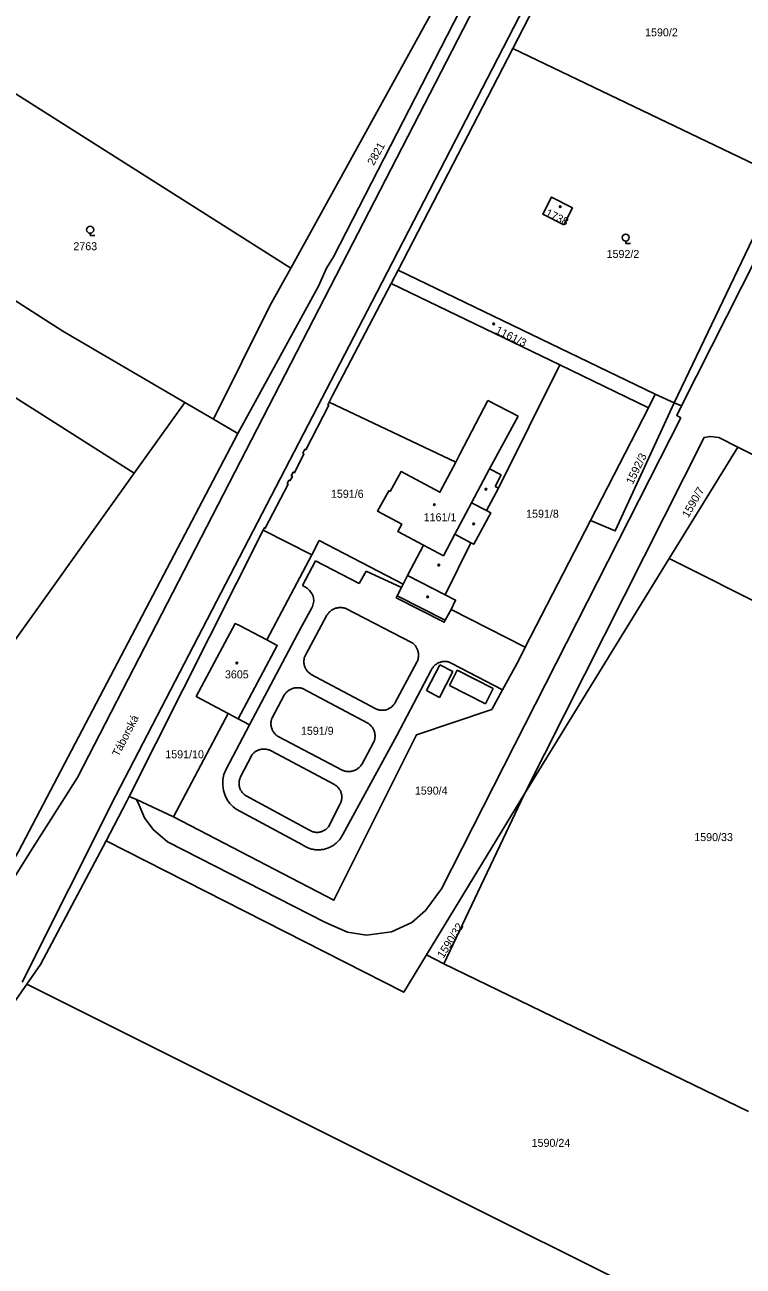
# Model space of a CAD drawing. Extents: x -679220 to -673243, y -1075091 to -1066557.
# Drawn here: x -677779.5 to -677626.7, y -1071876.4 to -1071612.6 of the extents above; entities that cross this region are included whole.
import ezdxf

# ---------------------------------------------------------------- set-up
doc = ezdxf.new("R2010")
doc.units = 0
for name, color, linetype in [('Hranice parcel', 7, 'Continuous'), ('Parcelní čísla', 7, 'Continuous'), ('Pop  PČ popisy', 7, 'Continuous'), ('Vnitřní kresba', 7, 'Continuous'), ('Značky budov', 7, 'Continuous'), ('Značky kultur', 7, 'Continuous')]:
    doc.layers.add(name, color=color, linetype=linetype)

msp = doc.modelspace()

# ---------------------------------------------------------------- linework, layer by layer
at = {"layer": 'Hranice parcel'}
for p, q in [((-677675.7, -1071617.62), (-677659.4, -1071586.1)), ((-677675.7, -1071617.62), (-677700.06, -1071664.74)), ((-677618.5, -1071645.05), (-677675.7, -1071617.62)), ((-677793.05, -1071619.95), (-677722.95, -1071664.32)), ((-677618.5, -1071645.05), (-677641.36, -1071692.91)), ((-677701.57, -1071667.56), (-677700.06, -1071664.74)), ((-677700.06, -1071664.74), (-677645.4, -1071691.12)), ((-677756.22, -1071707.84), (-677819.64, -1071667.71)), ((-677665.7, -1071684.86), (-677701.57, -1071667.56)), ((-677646.86, -1071693.97), (-677665.7, -1071684.86)), ((-677646.86, -1071693.97), (-677645.4, -1071691.12)), ((-677645.4, -1071691.12), (-677641.36, -1071692.91)), ((-677745.49, -1071692.83), (-677756.22, -1071707.84)), ((-677739.36, -1071696.41), (-677745.49, -1071692.83)), ((-677659.15, -1071717.9), (-677646.86, -1071693.97)), ((-677739.36, -1071696.41), (-677734.17, -1071699.43)), ((-677627.85, -1071702.34), (-677642.42, -1071725.99)), ((-677627.85, -1071702.34), (-677620.62, -1071705.96)), ((-677756.22, -1071707.84), (-677824.86, -1071803.81)), ((-677659.15, -1071717.9), (-677673.05, -1071744.83)), ((-677728.78, -1071719.96), (-677757.32, -1071776.61)), ((-677728.78, -1071719.96), (-677718.47, -1071725.21)), ((-677718.47, -1071725.21), (-677728.03, -1071743.31)), ((-677642.42, -1071725.99), (-677673.25, -1071776.04)), ((-677576.6, -1071759.04), (-677642.42, -1071725.99)), ((-677688.85, -1071736.82), (-677673.05, -1071744.83)), ((-677736.28, -1071758.92), (-677747.89, -1071780.9)), ((-677694.09, -1071810.25), (-677673.25, -1071776.04)), ((-677690.35, -1071812.12), (-677673.25, -1071776.04)), ((-677755.75, -1071777.25), (-677757.32, -1071776.61)), ((-677747.89, -1071780.9), (-677755.75, -1071777.25)), ((-677690.35, -1071812.12), (-677694.09, -1071810.25)), ((-677625.55, -1071843.55), (-677690.35, -1071812.12))]:
    msp.add_line(p, q, dxfattribs=at)
for points in [[(-677698.2, -1071587.54), (-677691.4, -1071597.52), (-677689.84, -1071604.27), (-677722.95, -1071664.32)], [(-677679.36, -1071592.98), (-677680.93, -1071595.81), (-677681.57, -1071599.11), (-677713.84, -1071661.87), (-677715.32, -1071664.31), (-677717.06, -1071668.11), (-677734.17, -1071699.43)], [(-677664.83, -1071655.1), (-677663.03, -1071651.51), (-677667.46, -1071649.22), (-677669.29, -1071652.86), (-677664.83, -1071655.1)], [(-677811.07, -1071652.31), (-677771.4, -1071677.73), (-677745.49, -1071692.83)], [(-677722.95, -1071664.32), (-677727.35, -1071672.3), (-677739.36, -1071696.41)], [(-677701.57, -1071667.56), (-677714.05, -1071691.4), (-677714.77, -1071692.82)], [(-677688.85, -1071736.82), (-677687.88, -1071734.84), (-677690.1, -1071733.71), (-677684.65, -1071722.65), (-677684.02, -1071722.98), (-677680.41, -1071716.3), (-677681.29, -1071715.83), (-677678.78, -1071711.06), (-677665.7, -1071684.86)], [(-677641.36, -1071692.91), (-677639.79, -1071693.55), (-677640.85, -1071695.65), (-677639.97, -1071696.12), (-677690.9, -1071796.21), (-677694.24, -1071800.78), (-677697.21, -1071803.39), (-677701.52, -1071805.32), (-677706.8, -1071806.02), (-677710.87, -1071805.39), (-677715.51, -1071803.35), (-677749.17, -1071786.23), (-677752.18, -1071783.61), (-677754.07, -1071781.12), (-677755.18, -1071778.44), (-677755.75, -1071777.25)], [(-677714.77, -1071692.82), (-677715.03, -1071693.32), (-677714.85, -1071693.41), (-677719.75, -1071702.9), (-677719.93, -1071702.81), (-677720.36, -1071703.65), (-677720.18, -1071703.74), (-677722.17, -1071707.77), (-677722.42, -1071707.64), (-677722.83, -1071708.44), (-677722.58, -1071708.56), (-677723.14, -1071709.48), (-677723.32, -1071709.39), (-677723.69, -1071710.1), (-677723.5, -1071710.19), (-677728.35, -1071719.57), (-677728.53, -1071719.48), (-677728.78, -1071719.96)], [(-677714.77, -1071692.82), (-677687.83, -1071705.51), (-677691.21, -1071711.92), (-677699.48, -1071707.54), (-677701.8, -1071711.75), (-677702.06, -1071711.6), (-677704.47, -1071715.98), (-677699.33, -1071718.71), (-677700.16, -1071720.29), (-677694.72, -1071723.15), (-677698.11, -1071729.64), (-677699.04, -1071731.47)], [(-677641.36, -1071692.91), (-677653.91, -1071720.16), (-677659.15, -1071717.9)], [(-677734.17, -1071699.43), (-677780.84, -1071788.29), (-677785.81, -1071796.6), (-677796.28, -1071814.23), (-677801.03, -1071820.85)], [(-677673.25, -1071776.04), (-677635.03, -1071700.33), (-677633.76, -1071700.05), (-677631.86, -1071700.33), (-677627.85, -1071702.34)], [(-677718.47, -1071725.21), (-677716.89, -1071722.21), (-677699.04, -1071731.47)], [(-677699.04, -1071731.47), (-677699.41, -1071732.17), (-677700.29, -1071733.93), (-677700.51, -1071734.35), (-677690.28, -1071739.55), (-677690.07, -1071739.14), (-677688.85, -1071736.82)], [(-677736.28, -1071758.92), (-677743.02, -1071755.33), (-677734.77, -1071739.82), (-677733.82, -1071740.27), (-677728.03, -1071743.31)], [(-677728.03, -1071743.31), (-677725.82, -1071744.47), (-677734.15, -1071760.05), (-677736.28, -1071758.92)], [(-677673.05, -1071744.83), (-677674.41, -1071747.63), (-677677.87, -1071753.9), (-677680.19, -1071758.12), (-677696.22, -1071763.45), (-677713.74, -1071798.64), (-677747.89, -1071780.9)], [(-677757.32, -1071776.61), (-677757.9, -1071777.68), (-677762.22, -1071786)], [(-677779.1, -1071816.48), (-677776.17, -1071812.28), (-677762.22, -1071786)], [(-677762.22, -1071786), (-677698.91, -1071818.16), (-677694.09, -1071810.25)], [(-677809.4, -1071859.4), (-677801.45, -1071848.53), (-677779.1, -1071816.48)], [(-677576, -1071917.67), (-677677.67, -1071867.11), (-677779.1, -1071816.48)]]:
    msp.add_lwpolyline(points, dxfattribs=at)
at = {"layer": 'Vnitřní kresba'}
for p, q in [((-677658.49, -1071559.68), (-677713.36, -1071666.01)), ((-677704.66, -1071669.46), (-677649.28, -1071562.45)), ((-677601.83, -1071618.35), (-677639.79, -1071693.55)), ((-677713.36, -1071666.01), (-677768.3, -1071772.54)), ((-677760.23, -1071776.53), (-677704.66, -1071669.46)), ((-677686.96, -1071703.87), (-677681.03, -1071692.44)), ((-677681.03, -1071692.44), (-677674.59, -1071695.73)), ((-677674.59, -1071695.73), (-677680.66, -1071706.92)), ((-677686.96, -1071703.87), (-677687.83, -1071705.51)), ((-677680.66, -1071706.92), (-677684.47, -1071714.15)), ((-677680.66, -1071706.92), (-677678.19, -1071708.23)), ((-677678.19, -1071708.23), (-677679.48, -1071710.69)), ((-677679.48, -1071710.69), (-677678.78, -1071711.06)), ((-677684.47, -1071714.15), (-677688.02, -1071720.87)), ((-677684.47, -1071714.15), (-677681.29, -1071715.83)), ((-677690.42, -1071725.42), (-677694.72, -1071723.15)), ((-677688.02, -1071720.87), (-677690.42, -1071725.42)), ((-677688.02, -1071720.87), (-677684.65, -1071722.65)), ((-677720.43, -1071731.72), (-677717.67, -1071726.5)), ((-677717.67, -1071726.5), (-677708.37, -1071731.35)), ((-677708.37, -1071731.35), (-677706.91, -1071728.7)), ((-677706.91, -1071728.7), (-677699.41, -1071732.17)), ((-677690.1, -1071733.71), (-677698.11, -1071729.64)), ((-677719.43, -1071732.34), (-677720.43, -1071731.72)), ((-677719.43, -1071732.34), (-677718.92, -1071732.79)), ((-677718.92, -1071732.79), (-677718.46, -1071733.42)), ((-677718.46, -1071733.42), (-677718.2, -1071734.01)), ((-677720.84, -1071740.86), (-677718.42, -1071736.47)), ((-677718.29, -1071736.19), (-677718.42, -1071736.47)), ((-677718.14, -1071735.64), (-677718.29, -1071736.19)), ((-677718.2, -1071734.01), (-677718.12, -1071734.38)), ((-677718.06, -1071735.08), (-677718.14, -1071735.64)), ((-677718.12, -1071734.38), (-677718.06, -1071735.08)), ((-677690.07, -1071739.14), (-677700.29, -1071733.93)), ((-677719.83, -1071746.56), (-677715.23, -1071738.05)), ((-677711.35, -1071736.59), (-677697.11, -1071743.91)), ((-677731.72, -1071761.34), (-677720.84, -1071740.86)), ((-677696.09, -1071748.02), (-677700.74, -1071756.62)), ((-677691.24, -1071748.63), (-677694.09, -1071754.07)), ((-677688.45, -1071750.01), (-677691.24, -1071748.63)), ((-677677.87, -1071753.9), (-677688.65, -1071748.29)), ((-677704.86, -1071757.93), (-677718.7, -1071750.56)), ((-677700.4, -1071763.63), (-677693.06, -1071749.76)), ((-677691.29, -1071755.55), (-677688.45, -1071750.01)), ((-677689.2, -1071753.01), (-677687.53, -1071749.76)), ((-677687.53, -1071749.76), (-677679.88, -1071753.61)), ((-677720.26, -1071753.68), (-677706.56, -1071760.97)), ((-677694.09, -1071754.07), (-677691.29, -1071755.55)), ((-677681.5, -1071756.87), (-677689.2, -1071753.01)), ((-677679.88, -1071753.61), (-677681.5, -1071756.87)), ((-677726.89, -1071759.84), (-677724.33, -1071755.03)), ((-677731.72, -1071761.34), (-677734.15, -1071760.05)), ((-677731.72, -1071761.34), (-677736.7, -1071770.76)), ((-677725.63, -1071763.83), (-677711.86, -1071771.03)), ((-677711.87, -1071784.68), (-677700.4, -1071763.63)), ((-677707.84, -1071769.75), (-677705.31, -1071765.13)), ((-677733.59, -1071772.41), (-677731.3, -1071767.92)), ((-677727.11, -1071766.88), (-677713.63, -1071774.06)), ((-677737.14, -1071771.93), (-677736.7, -1071770.76)), ((-677778.26, -1071788.24), (-677768.3, -1071772.54)), ((-677737.4, -1071774.19), (-677737.36, -1071772.99)), ((-677737.36, -1071772.99), (-677737.14, -1071771.93)), ((-677737.24, -1071775.34), (-677737.4, -1071774.19)), ((-677736.89, -1071776.37), (-677737.24, -1071775.34)), ((-677760.23, -1071776.53), (-677780.06, -1071816)), ((-677736.45, -1071777.26), (-677736.89, -1071776.37)), ((-677735.9, -1071778.05), (-677736.45, -1071777.26)), ((-677735.18, -1071778.79), (-677735.9, -1071778.05)), ((-677719.09, -1071783.67), (-677732.43, -1071776.42)), ((-677712.41, -1071778.12), (-677714.94, -1071783.02)), ((-677734.55, -1071779.28), (-677735.18, -1071778.79)), ((-677720.43, -1071786.85), (-677734.55, -1071779.28)), ((-677795.14, -1071815.04), (-677778.26, -1071788.24))]:
    msp.add_line(p, q, dxfattribs=at)
for points in [[(-677715.23, -1071738.05), (-677715.14, -1071737.92), (-677715.05, -1071737.79), (-677714.95, -1071737.66), (-677714.85, -1071737.54), (-677714.74, -1071737.42), (-677714.62, -1071737.31), (-677714.51, -1071737.21), (-677714.38, -1071737.11), (-677714.25, -1071737.01), (-677714.12, -1071736.93), (-677713.98, -1071736.85), (-677713.84, -1071736.77), (-677713.69, -1071736.71), (-677713.54, -1071736.65), (-677713.39, -1071736.59), (-677713.24, -1071736.55), (-677713.08, -1071736.51), (-677712.93, -1071736.48), (-677712.77, -1071736.46), (-677712.61, -1071736.44), (-677712.45, -1071736.43), (-677712.29, -1071736.43), (-677712.13, -1071736.44), (-677711.97, -1071736.46), (-677711.82, -1071736.48), (-677711.66, -1071736.51), (-677711.5, -1071736.55), (-677711.35, -1071736.59)], [(-677697.11, -1071743.91), (-677696.98, -1071744.01), (-677696.86, -1071744.11), (-677696.74, -1071744.22), (-677696.63, -1071744.33), (-677696.53, -1071744.45), (-677696.43, -1071744.57), (-677696.34, -1071744.7), (-677696.25, -1071744.83), (-677696.17, -1071744.97), (-677696.09, -1071745.11), (-677696.03, -1071745.25), (-677695.97, -1071745.4), (-677695.91, -1071745.55), (-677695.87, -1071745.7), (-677695.83, -1071745.85), (-677695.8, -1071746.01), (-677695.78, -1071746.17), (-677695.76, -1071746.33), (-677695.75, -1071746.49), (-677695.75, -1071746.64), (-677695.76, -1071746.8), (-677695.77, -1071746.96), (-677695.8, -1071747.12), (-677695.83, -1071747.27), (-677695.86, -1071747.43), (-677695.91, -1071747.58), (-677695.96, -1071747.73), (-677696.02, -1071747.88), (-677696.09, -1071748.02)], [(-677718.7, -1071750.56), (-677718.83, -1071750.47), (-677718.96, -1071750.38), (-677719.08, -1071750.28), (-677719.19, -1071750.17), (-677719.3, -1071750.06), (-677719.41, -1071749.94), (-677719.51, -1071749.82), (-677719.6, -1071749.7), (-677719.68, -1071749.56), (-677719.76, -1071749.43), (-677719.84, -1071749.29), (-677719.9, -1071749.15), (-677719.96, -1071749), (-677720.01, -1071748.85), (-677720.05, -1071748.7), (-677720.09, -1071748.55), (-677720.11, -1071748.39), (-677720.13, -1071748.24), (-677720.14, -1071748.08), (-677720.15, -1071747.92), (-677720.14, -1071747.77), (-677720.13, -1071747.61), (-677720.11, -1071747.46), (-677720.08, -1071747.3), (-677720.05, -1071747.15), (-677720, -1071747), (-677719.95, -1071746.85), (-677719.9, -1071746.7), (-677719.83, -1071746.56)], [(-677693.06, -1071749.76), (-677692.99, -1071749.62), (-677692.92, -1071749.48), (-677692.83, -1071749.34), (-677692.74, -1071749.21), (-677692.65, -1071749.08), (-677692.55, -1071748.96), (-677692.44, -1071748.85), (-677692.33, -1071748.74), (-677692.21, -1071748.63), (-677692.09, -1071748.53), (-677691.96, -1071748.44), (-677691.82, -1071748.35), (-677691.69, -1071748.28), (-677691.55, -1071748.2), (-677691.4, -1071748.14), (-677691.25, -1071748.08), (-677691.1, -1071748.03), (-677690.95, -1071747.99), (-677690.8, -1071747.95), (-677690.64, -1071747.93), (-677690.48, -1071747.91), (-677690.33, -1071747.9), (-677690.17, -1071747.89), (-677690.01, -1071747.9), (-677689.85, -1071747.91), (-677689.69, -1071747.93), (-677689.54, -1071747.96), (-677689.38, -1071748), (-677689.23, -1071748.04), (-677689.08, -1071748.09), (-677688.93, -1071748.15), (-677688.79, -1071748.22), (-677688.65, -1071748.29)], [(-677724.33, -1071755.03), (-677724.24, -1071754.89), (-677724.14, -1071754.76), (-677724.03, -1071754.64), (-677723.92, -1071754.51), (-677723.8, -1071754.4), (-677723.68, -1071754.29), (-677723.55, -1071754.18), (-677723.42, -1071754.09), (-677723.28, -1071754), (-677723.14, -1071753.91), (-677722.99, -1071753.83), (-677722.84, -1071753.76), (-677722.69, -1071753.7), (-677722.53, -1071753.64), (-677722.37, -1071753.59), (-677722.21, -1071753.55), (-677722.05, -1071753.52), (-677721.89, -1071753.5), (-677721.72, -1071753.48), (-677721.56, -1071753.47), (-677721.39, -1071753.47), (-677721.23, -1071753.48), (-677721.06, -1071753.49), (-677720.9, -1071753.51), (-677720.74, -1071753.54), (-677720.58, -1071753.58), (-677720.42, -1071753.63), (-677720.26, -1071753.68)], [(-677700.74, -1071756.62), (-677700.82, -1071756.75), (-677700.9, -1071756.89), (-677700.99, -1071757.01), (-677701.08, -1071757.13), (-677701.18, -1071757.25), (-677701.29, -1071757.36), (-677701.4, -1071757.47), (-677701.52, -1071757.57), (-677701.64, -1071757.66), (-677701.77, -1071757.75), (-677701.9, -1071757.83), (-677702.04, -1071757.91), (-677702.17, -1071757.98), (-677702.32, -1071758.04), (-677702.46, -1071758.09), (-677702.61, -1071758.14), (-677702.76, -1071758.18), (-677702.91, -1071758.21), (-677703.06, -1071758.23), (-677703.21, -1071758.25), (-677703.37, -1071758.26), (-677703.52, -1071758.26), (-677703.68, -1071758.25), (-677703.83, -1071758.24), (-677703.98, -1071758.22), (-677704.13, -1071758.19), (-677704.28, -1071758.15), (-677704.43, -1071758.11), (-677704.58, -1071758.06), (-677704.72, -1071758), (-677704.86, -1071757.93)], [(-677725.63, -1071763.83), (-677725.76, -1071763.74), (-677725.89, -1071763.65), (-677726.01, -1071763.55), (-677726.13, -1071763.45), (-677726.24, -1071763.34), (-677726.35, -1071763.22), (-677726.45, -1071763.1), (-677726.54, -1071762.98), (-677726.63, -1071762.85), (-677726.72, -1071762.72), (-677726.79, -1071762.58), (-677726.86, -1071762.44), (-677726.92, -1071762.29), (-677726.98, -1071762.14), (-677727.02, -1071761.99), (-677727.06, -1071761.84), (-677727.1, -1071761.69), (-677727.12, -1071761.53), (-677727.14, -1071761.38), (-677727.15, -1071761.22), (-677727.15, -1071761.06), (-677727.14, -1071760.91), (-677727.13, -1071760.75), (-677727.11, -1071760.59), (-677727.08, -1071760.44), (-677727.04, -1071760.29), (-677727, -1071760.14), (-677726.95, -1071759.99), (-677726.89, -1071759.84)], [(-677706.56, -1071760.97), (-677706.43, -1071761.06), (-677706.3, -1071761.15), (-677706.17, -1071761.25), (-677706.05, -1071761.35), (-677705.94, -1071761.46), (-677705.83, -1071761.58), (-677705.73, -1071761.7), (-677705.63, -1071761.82), (-677705.54, -1071761.95), (-677705.46, -1071762.09), (-677705.38, -1071762.22), (-677705.31, -1071762.37), (-677705.24, -1071762.51), (-677705.19, -1071762.66), (-677705.14, -1071762.81), (-677705.1, -1071762.96), (-677705.06, -1071763.12), (-677705.03, -1071763.27), (-677705.02, -1071763.43), (-677705, -1071763.59), (-677705, -1071763.75), (-677705, -1071763.91), (-677705.02, -1071764.06), (-677705.04, -1071764.22), (-677705.06, -1071764.38), (-677705.1, -1071764.53), (-677705.14, -1071764.69), (-677705.19, -1071764.84), (-677705.25, -1071764.99), (-677705.31, -1071765.13)], [(-677731.3, -1071767.92), (-677731.21, -1071767.79), (-677731.11, -1071767.67), (-677731.01, -1071767.55), (-677730.9, -1071767.43), (-677730.79, -1071767.32), (-677730.67, -1071767.22), (-677730.54, -1071767.12), (-677730.41, -1071767.03), (-677730.28, -1071766.95), (-677730.14, -1071766.87), (-677730, -1071766.8), (-677729.86, -1071766.74), (-677729.71, -1071766.68), (-677729.56, -1071766.63), (-677729.41, -1071766.59), (-677729.25, -1071766.55), (-677729.1, -1071766.53), (-677728.94, -1071766.51), (-677728.78, -1071766.5), (-677728.62, -1071766.49), (-677728.47, -1071766.5), (-677728.31, -1071766.51), (-677728.15, -1071766.53), (-677728, -1071766.56), (-677727.84, -1071766.59), (-677727.69, -1071766.64), (-677727.54, -1071766.69), (-677727.4, -1071766.74), (-677727.25, -1071766.81), (-677727.11, -1071766.88)], [(-677707.84, -1071769.75), (-677707.93, -1071769.88), (-677708.02, -1071770.01), (-677708.12, -1071770.13), (-677708.23, -1071770.25), (-677708.34, -1071770.36), (-677708.46, -1071770.46), (-677708.58, -1071770.56), (-677708.71, -1071770.66), (-677708.84, -1071770.75), (-677708.97, -1071770.83), (-677709.11, -1071770.91), (-677709.25, -1071770.98), (-677709.4, -1071771.04), (-677709.54, -1071771.09), (-677709.69, -1071771.14), (-677709.85, -1071771.18), (-677710, -1071771.21), (-677710.16, -1071771.24), (-677710.31, -1071771.26), (-677710.47, -1071771.27), (-677710.63, -1071771.27), (-677710.79, -1071771.27), (-677710.94, -1071771.26), (-677711.1, -1071771.24), (-677711.26, -1071771.21), (-677711.41, -1071771.18), (-677711.56, -1071771.14), (-677711.71, -1071771.09), (-677711.86, -1071771.03)], [(-677732.43, -1071776.42), (-677732.56, -1071776.34), (-677732.69, -1071776.25), (-677732.81, -1071776.16), (-677732.93, -1071776.06), (-677733.04, -1071775.96), (-677733.15, -1071775.84), (-677733.25, -1071775.73), (-677733.34, -1071775.61), (-677733.43, -1071775.48), (-677733.51, -1071775.35), (-677733.59, -1071775.22), (-677733.66, -1071775.08), (-677733.72, -1071774.94), (-677733.77, -1071774.8), (-677733.82, -1071774.65), (-677733.86, -1071774.5), (-677733.89, -1071774.35), (-677733.91, -1071774.2), (-677733.93, -1071774.05), (-677733.94, -1071773.89), (-677733.94, -1071773.74), (-677733.93, -1071773.58), (-677733.91, -1071773.43), (-677733.89, -1071773.28), (-677733.86, -1071773.13), (-677733.82, -1071772.98), (-677733.77, -1071772.83), (-677733.72, -1071772.69), (-677733.66, -1071772.55), (-677733.59, -1071772.41)], [(-677713.63, -1071774.06), (-677713.5, -1071774.14), (-677713.37, -1071774.23), (-677713.24, -1071774.32), (-677713.12, -1071774.42), (-677713.01, -1071774.53), (-677712.9, -1071774.64), (-677712.79, -1071774.75), (-677712.7, -1071774.88), (-677712.61, -1071775), (-677712.52, -1071775.13), (-677712.44, -1071775.27), (-677712.37, -1071775.41), (-677712.31, -1071775.55), (-677712.25, -1071775.7), (-677712.2, -1071775.84), (-677712.16, -1071776), (-677712.13, -1071776.15), (-677712.1, -1071776.3), (-677712.09, -1071776.46), (-677712.08, -1071776.61), (-677712.08, -1071776.77), (-677712.08, -1071776.93), (-677712.1, -1071777.08), (-677712.12, -1071777.23), (-677712.15, -1071777.39), (-677712.18, -1071777.54), (-677712.23, -1071777.69), (-677712.28, -1071777.83), (-677712.34, -1071777.98), (-677712.41, -1071778.12)], [(-677714.94, -1071783.02), (-677715.04, -1071783.14), (-677715.14, -1071783.25), (-677715.25, -1071783.36), (-677715.36, -1071783.47), (-677715.48, -1071783.56), (-677715.61, -1071783.66), (-677715.74, -1071783.74), (-677715.87, -1071783.82), (-677716.01, -1071783.89), (-677716.15, -1071783.96), (-677716.29, -1071784.01), (-677716.44, -1071784.06), (-677716.58, -1071784.11), (-677716.73, -1071784.14), (-677716.89, -1071784.17), (-677717.04, -1071784.19), (-677717.19, -1071784.2), (-677717.35, -1071784.21), (-677717.5, -1071784.2), (-677717.66, -1071784.19), (-677717.81, -1071784.17), (-677717.96, -1071784.15), (-677718.11, -1071784.11), (-677718.26, -1071784.07), (-677718.41, -1071784.02), (-677718.55, -1071783.97), (-677718.69, -1071783.9), (-677718.83, -1071783.83), (-677718.96, -1071783.75), (-677719.09, -1071783.67)], [(-677711.87, -1071784.68), (-677711.97, -1071784.87), (-677712.07, -1071785.06), (-677712.19, -1071785.24), (-677712.3, -1071785.42), (-677712.43, -1071785.59), (-677712.56, -1071785.76), (-677712.7, -1071785.92), (-677712.84, -1071786.08), (-677712.99, -1071786.23), (-677713.14, -1071786.38), (-677713.3, -1071786.52), (-677713.47, -1071786.66), (-677713.64, -1071786.79), (-677713.81, -1071786.91), (-677713.99, -1071787.03), (-677714.17, -1071787.14), (-677714.36, -1071787.24), (-677714.55, -1071787.33), (-677714.74, -1071787.42), (-677714.94, -1071787.51), (-677715.14, -1071787.58), (-677715.34, -1071787.65), (-677715.55, -1071787.71), (-677715.75, -1071787.76), (-677715.96, -1071787.81), (-677716.17, -1071787.84), (-677716.38, -1071787.87), (-677716.6, -1071787.89), (-677716.81, -1071787.91), (-677717.02, -1071787.91), (-677717.24, -1071787.91), (-677717.45, -1071787.9), (-677717.66, -1071787.88), (-677717.87, -1071787.86), (-677718.09, -1071787.83), (-677718.29, -1071787.79), (-677718.5, -1071787.74), (-677718.71, -1071787.68), (-677718.91, -1071787.62), (-677719.11, -1071787.55), (-677719.31, -1071787.47), (-677719.51, -1071787.38), (-677719.7, -1071787.29), (-677719.89, -1071787.19), (-677720.07, -1071787.08), (-677720.25, -1071786.97), (-677720.43, -1071786.85)]]:
    msp.add_lwpolyline(points, dxfattribs=at)
at = {"layer": 'Značky budov'}
for centre in [(-677665.62, -1071651.24), (-677679.79, -1071676.15), (-677681.43, -1071711.29), (-677692.39, -1071714.58), (-677684.02, -1071718.65), (-677691.45, -1071727.42), (-677693.8, -1071734.16), (-677734.4, -1071748.23)]:
    msp.add_circle(centre, 0.175, dxfattribs=at)
at = {"layer": 'Značky kultur'}
for p, q in [((-677765.6, -1071656.9), (-677765.6, -1071657.4)), ((-677765.6, -1071657.4), (-677764.6, -1071657.4)), ((-677651.69, -1071658.57), (-677651.69, -1071659.07)), ((-677651.69, -1071659.07), (-677650.69, -1071659.07))]:
    msp.add_line(p, q, dxfattribs=at)
for centre in [(-677765.6, -1071656.15), (-677651.69, -1071657.82)]:
    msp.add_circle(centre, 0.75, dxfattribs=at)

# ---------------------------------------------------------------- texts
at = {"layer": 'Parcelní čísla'}
for s, p in [('1590/2', (-677647.57, -1071615.05)), ('2763', (-677769.17, -1071660.5)), ('1592/2', (-677655.75, -1071662.14)), ('1591/6', (-677714.39, -1071713.11)), ('1161/1', (-677694.66, -1071718.09)), ('1591/8', (-677672.87, -1071717.34)), ('3605', (-677736.94, -1071751.48)), ('1591/9', (-677720.77, -1071763.47)), ('1591/10', (-677749.62, -1071768.46)), ('1590/4', (-677696.53, -1071776.18)), ('1590/33', (-677637.11, -1071786.06)), ('1590/24', (-677671.7, -1071851.03))]:
    msp.add_text(s, height=1.7, dxfattribs=at).set_placement(p)
for s, rotation, p in [('2821', 61, (-677705.28, -1071642.63)), ('1738', 334, (-677668.92, -1071653.14)), ('1161/3', 334, (-677679.55, -1071678.06)), ('1592/3', 64, (-677650.2, -1071710.4)), ('1590/7', 60, (-677638.37, -1071717.48)), ('1590/32', 58, (-677690.47, -1071811.1))]:
    msp.add_text(s, height=1.7, rotation=rotation, dxfattribs=at).set_placement(p)
at = {"layer": 'Pop  PČ popisy'}
msp.add_text('Táborská', height=1.7, rotation=63, dxfattribs=at).set_placement((-677759.53, -1071768.26))

doc.saveas('drawing.dxf')
